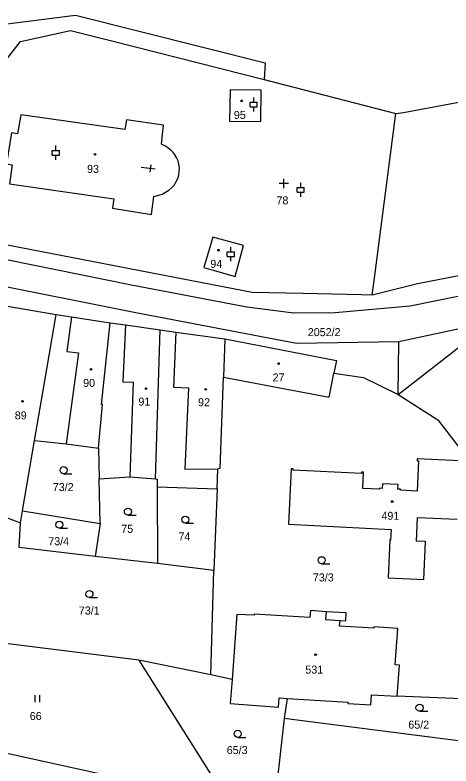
# Model space of a CAD drawing. Extents: x -794765 to -785424, y -1118958 to -1108731.
# Drawn here: x -788096.4 to -788003.9, y -1116478.9 to -1116319.5 of the extents above; entities that cross this region are included whole.
import ezdxf

# ---------------------------------------------------------------- set-up
doc = ezdxf.new("R2010")
doc.units = 0
for name, color, linetype in [('Level 66', 7, 'Continuous'), ('Level 75', 7, 'Continuous'), ('Level 76', 7, 'Continuous'), ('Level 77', 7, 'Continuous'), ('Level 79', 7, 'Continuous')]:
    doc.layers.add(name, color=color, linetype=linetype)

msp = doc.modelspace()

# ---------------------------------------------------------------- linework, layer by layer
at = {"layer": 'Level 66'}
for p, q in [((-788045.73, -1116337.98), (-788045.73, -1116336.98)), ((-788046.48, -1116337.98), (-788044.98, -1116337.98)), ((-788046.48, -1116338.98), (-788046.48, -1116337.98)), ((-788046.48, -1116338.98), (-788044.98, -1116338.98)), ((-788045.73, -1116339.98), (-788045.73, -1116338.98)), ((-788044.98, -1116338.98), (-788044.98, -1116337.98)), ((-788087.74, -1116348.2), (-788087.74, -1116347.2)), ((-788088.49, -1116348.2), (-788086.99, -1116348.2)), ((-788088.49, -1116349.2), (-788088.49, -1116348.2)), ((-788086.99, -1116349.2), (-788086.99, -1116348.2)), ((-788088.49, -1116349.2), (-788086.99, -1116349.2)), ((-788087.74, -1116350.2), (-788087.74, -1116349.2)), ((-788039.34, -1116356.24), (-788039.34, -1116354.24)), ((-788035.76, -1116356.07), (-788035.76, -1116355.07)), ((-788038.34, -1116355.24), (-788040.34, -1116355.24)), ((-788036.51, -1116356.07), (-788035.01, -1116356.07)), ((-788036.51, -1116357.07), (-788036.51, -1116356.07)), ((-788035.01, -1116357.07), (-788035.01, -1116356.07)), ((-788036.51, -1116357.07), (-788035.01, -1116357.07)), ((-788035.76, -1116358.07), (-788035.76, -1116357.07)), ((-788050.6, -1116369.73), (-788050.6, -1116368.73)), ((-788051.35, -1116369.73), (-788049.85, -1116369.73)), ((-788051.35, -1116370.73), (-788051.35, -1116369.73)), ((-788051.35, -1116370.73), (-788049.85, -1116370.73)), ((-788050.6, -1116371.73), (-788050.6, -1116370.73)), ((-788049.85, -1116370.73), (-788049.85, -1116369.73)), ((-788086.09, -1116416.86), (-788084.34, -1116416.86)), ((-788072.45, -1116425.66), (-788070.7, -1116425.66)), ((-788086.98, -1116428.43), (-788085.23, -1116428.43)), ((-788060.25, -1116427.37), (-788058.5, -1116427.37)), ((-788031.33, -1116435.97), (-788029.58, -1116435.97)), ((-788080.61, -1116443.16), (-788078.86, -1116443.16)), ((-788092.14, -1116465.35), (-788092.14, -1116463.85)), ((-788091.14, -1116465.35), (-788091.14, -1116463.85)), ((-788010.56, -1116467.28), (-788008.81, -1116467.28)), ((-788049.14, -1116472.83), (-788047.39, -1116472.83))]:
    msp.add_line(p, q, dxfattribs=at)
for centre in [(-788086.09, -1116416.11), (-788072.45, -1116424.91), (-788060.25, -1116426.62), (-788086.98, -1116427.68), (-788031.33, -1116435.22), (-788080.61, -1116442.41), (-788010.56, -1116466.53), (-788049.14, -1116472.08)]:
    msp.add_circle(centre, 0.75, dxfattribs=at)
at = {"layer": 'Level 75'}
for p, q in [((-788043.51, -1116333.19), (-788015.56, -1116340.35)), ((-788066.61, -1116417.95), (-788065.62, -1116386.32)), ((-788015.12, -1116400.05), (-787998.34, -1116386.95)), ((-788051.87, -1116388.25), (-788052.17, -1116396.35)), ((-788015.12, -1116400.05), (-788014.95, -1116388.89)), ((-788094.82, -1116424.73), (-788092.26, -1116409.81)), ((-788078.71, -1116411.45), (-788078.56, -1116417.96)), ((-788078.34, -1116427.43), (-788078.56, -1116417.96)), ((-788066.2, -1116419.66), (-788053.5, -1116420.08)), ((-788066.2, -1116419.66), (-788066.14, -1116435.91)), ((-788053.5, -1116420.08), (-788054.21, -1116437.38)), ((-788103.93, -1116424.04), (-788095.26, -1116427.29)), ((-788095.26, -1116427.29), (-788094.82, -1116424.73)), ((-788094.82, -1116424.73), (-788078.34, -1116427.43)), ((-788078.34, -1116427.43), (-788079.41, -1116434.45)), ((-788066.14, -1116435.91), (-788079.41, -1116434.45)), ((-788054.21, -1116437.38), (-788066.14, -1116435.91)), ((-788054.85, -1116459.59), (-788054.21, -1116437.38)), ((-788070.15, -1116456.47), (-788108.88, -1116451.59)), ((-788054.85, -1116459.59), (-788070.15, -1116456.47)), ((-788050.33, -1116460.52), (-788054.85, -1116459.59)), ((-788038.67, -1116464.56), (-788039.3, -1116468.86)), ((-788039.3, -1116468.86), (-788041.37, -1116487.28)), ((-787990.75, -1116475.07), (-788039.3, -1116468.86))]:
    msp.add_line(p, q, dxfattribs=at)
for points in [[(-788110.98, -1116320.69), (-788100.4, -1116321.61), (-788083.57, -1116319.47), (-788043.34, -1116329.62), (-788043.51, -1116333.19)], [(-788104.08, -1116336.38), (-788095.27, -1116325.08), (-788084.6, -1116322.77), (-788075.84, -1116324.92), (-788043.51, -1116333.19)], [(-788044.2, -1116342.07), (-788044.15, -1116335.4), (-788050.76, -1116335.38), (-788050.87, -1116342.02), (-788044.2, -1116342.07)], [(-788015.56, -1116340.35), (-788013.98, -1116340.14), (-787987.86, -1116335.25)], [(-788104.08, -1116336.38), (-788108.05, -1116361.45), (-788105.63, -1116365.59), (-788103.61, -1116367.18), (-788046.1, -1116378.3), (-788038.81, -1116378.46), (-788035.35, -1116378.54), (-788022.85, -1116378.83), (-788020.59, -1116378.86)], [(-788065.34, -1116346.88), (-788064.86, -1116342.89), (-788072.76, -1116341.74), (-788073.06, -1116343.77), (-788095.19, -1116340.68), (-788095.84, -1116344.71), (-788097.16, -1116344.45), (-788098.21, -1116351.08), (-788097, -1116351.26), (-788097.58, -1116355.3), (-788075.44, -1116358.49), (-788075.73, -1116360.48), (-788067.47, -1116361.8), (-788066.97, -1116357.98)], [(-788020.59, -1116378.86), (-788020.25, -1116376.38), (-788015.56, -1116340.35)], [(-788066.97, -1116357.98), (-788066.16, -1116357.82), (-788065.37, -1116357.56), (-788065.18, -1116357.48), (-788064.44, -1116357.1), (-788063.75, -1116356.64), (-788063.13, -1116356.1), (-788062.57, -1116355.49), (-788062.18, -1116354.84), (-788061.87, -1116354.15), (-788061.66, -1116353.43), (-788061.54, -1116352.68), (-788061.52, -1116351.92), (-788061.61, -1116351.17), (-788061.79, -1116350.43), (-788062.14, -1116349.71), (-788062.57, -1116349.03), (-788062.78, -1116348.76), (-788063.33, -1116348.17), (-788063.94, -1116347.66), (-788064.62, -1116347.23), (-788065.34, -1116346.88)], [(-788279.68, -1116369.68), (-788255.51, -1116372.91), (-788222.27, -1116376.2), (-788184.96, -1116374.64), (-788169.09, -1116371.97), (-788125.59, -1116364.93), (-788118.03, -1116366.65), (-788103.88, -1116370.26), (-788071.66, -1116376.73), (-788047.19, -1116381.42), (-788037.25, -1116382.67), (-788028.44, -1116382.62), (-788012.56, -1116381.23), (-787982.57, -1116375.12), (-787957.81, -1116369.21), (-787938.9, -1116364.93), (-787918.57, -1116359.78), (-787902.51, -1116353.37)], [(-787873.99, -1116354.2), (-787897.15, -1116362.5), (-787902.61, -1116363.72), (-787928.65, -1116369.79), (-787960.17, -1116377.12), (-788014.95, -1116388.89)], [(-788054.45, -1116366.61), (-788056.36, -1116373.05), (-788049.67, -1116374.99), (-788047.89, -1116368.42), (-788054.45, -1116366.61)], [(-788020.59, -1116378.86), (-788011.01, -1116376.49), (-787983.27, -1116371.1)], [(-788014.95, -1116388.89), (-788036.64, -1116389.18), (-788070.79, -1116382.68), (-788103.44, -1116376.2), (-788117.24, -1116374.47), (-788120.83, -1116373.97), (-788135.12, -1116373.51), (-788155.68, -1116377.39), (-788186.34, -1116383.39), (-788190.87, -1116384.17), (-788201.33, -1116384.26), (-788234.5, -1116382.6)], [(-788103.27, -1116378.99), (-788098.18, -1116380.06), (-788098.42, -1116381.18), (-788087.66, -1116383.04)], [(-788092.26, -1116409.81), (-788090.51, -1116399.62), (-788087.66, -1116383.04)], [(-788087.66, -1116383.04), (-788084.4, -1116383.53), (-788076.2, -1116384.79)], [(-788078.71, -1116411.45), (-788077.83, -1116402.16), (-788078.08, -1116402.14), (-788076.2, -1116384.79)], [(-788076.2, -1116384.79), (-788072.94, -1116385.26), (-788065.62, -1116386.32)], [(-788065.62, -1116386.32), (-788062.27, -1116386.79), (-788051.87, -1116388.25)], [(-788051.87, -1116388.25), (-788028.19, -1116392.84), (-788028.72, -1116395.5)], [(-788053.5, -1116420.08), (-788053.33, -1116415.81), (-788052.88, -1116415.7), (-788052.17, -1116396.35)], [(-788052.17, -1116396.35), (-788029.75, -1116400.64), (-788028.72, -1116395.5)], [(-788028.72, -1116395.5), (-788022.48, -1116396.45), (-788015.12, -1116400.05)], [(-788015.12, -1116400.05), (-788006.65, -1116405.45), (-788000.06, -1116414.07), (-787995.42, -1116423.48), (-787992.45, -1116431.22), (-787989.3, -1116443.49), (-787985.23, -1116460.93), (-787984.99, -1116467.12)], [(-788092.26, -1116409.81), (-788085.52, -1116410.53), (-788078.71, -1116411.45)], [(-788002.01, -1116414.1), (-788011.05, -1116413.71), (-788011.07, -1116414.13), (-788010.78, -1116414.14), (-788011.08, -1116420.54), (-788014.63, -1116420.36), (-788014.62, -1116420.15), (-788015.15, -1116420.13), (-788015.1, -1116419.15), (-788018.43, -1116418.99), (-788018.48, -1116419.97), (-788019.03, -1116419.93), (-788019.03, -1116420.16), (-788022.58, -1116419.99), (-788022.42, -1116416.53), (-788022.85, -1116416.5), (-788022.87, -1116416.81), (-788037.36, -1116416.12), (-788037.35, -1116415.82)], [(-788037.35, -1116415.82), (-788037.79, -1116415.8), (-788038.33, -1116427.56), (-788016.58, -1116428.67), (-788016.7, -1116430.94), (-788016.86, -1116430.93), (-788017.2, -1116438.95), (-788009.63, -1116439.33), (-788009.29, -1116431.24), (-788011.21, -1116431.17), (-788010.98, -1116426.15), (-788002.56, -1116426.54)], [(-788078.56, -1116417.96), (-788072.05, -1116417.55), (-788066.61, -1116417.95)], [(-788066.61, -1116417.95), (-788066.21, -1116417.98), (-788066.2, -1116419.66)], [(-788079.41, -1116434.45), (-788095.52, -1116432.53), (-788095.26, -1116427.29)], [(-788015.27, -1116464.09), (-788014.84, -1116457.51), (-788015.74, -1116457.45), (-788015.19, -1116449.72), (-788020.27, -1116449.35), (-788020.29, -1116449.67), (-788027.56, -1116449.2), (-788027.43, -1116448.01), (-788026.2, -1116448.09), (-788026.1, -1116446.42), (-788030.4, -1116446.2), (-788033.68, -1116445.88), (-788033.83, -1116447.38), (-788045.64, -1116446.66), (-788045.66, -1116446.92), (-788049.32, -1116446.74), (-788050.33, -1116460.52)], [(-788070.15, -1116456.47), (-788052.14, -1116485), (-788052.25, -1116486.37)], [(-788050.33, -1116460.52), (-788050.71, -1116465.66), (-788040.5, -1116466.4), (-788040.37, -1116464.45), (-788038.67, -1116464.56)], [(-788038.67, -1116464.56), (-788025.73, -1116465.39), (-788025.75, -1116465.64), (-788020.88, -1116465.96), (-788020.73, -1116463.77), (-788015.27, -1116464.09)], [(-787990.75, -1116475.07), (-787991.37, -1116465.05), (-788015.27, -1116464.09)], [(-788052.25, -1116486.37), (-788061.11, -1116484.42), (-788104.94, -1116474.74)]]:
    msp.add_lwpolyline(points, dxfattribs=at)
at = {"layer": 'Level 77'}
for p, q in [((-788084.4, -1116383.53), (-788085.38, -1116390.88)), ((-788072.94, -1116385.26), (-788073.55, -1116397.34)), ((-788062.27, -1116386.79), (-788062.77, -1116398.45)), ((-788082.93, -1116391.21), (-788085.52, -1116410.53)), ((-788085.38, -1116390.88), (-788082.93, -1116391.21)), ((-788073.55, -1116397.34), (-788071.3, -1116397.43)), ((-788071.3, -1116397.43), (-788072.05, -1116417.55)), ((-788062.77, -1116398.45), (-788059.56, -1116398.6)), ((-788059.56, -1116398.6), (-788060.33, -1116415.86)), ((-788060.33, -1116415.86), (-788053.33, -1116415.81)), ((-788030.4, -1116446.2), (-788030.5, -1116447.83)), ((-788030.5, -1116447.83), (-788027.43, -1116448.01))]:
    msp.add_line(p, q, dxfattribs=at)
at = {"layer": 'Level 79'}
for p, q in [((-788066.67, -1116352.18), (-788069.65, -1116351.81)), ((-788067.58, -1116351.31), (-788067.76, -1116352.8))]:
    msp.add_line(p, q, dxfattribs=at)
for centre in [(-788048.3, -1116337.7), (-788079.44, -1116349.05), (-788053.21, -1116369.41), (-788040.44, -1116393.46), (-788080.29, -1116394.68), (-788068.61, -1116398.79), (-788055.93, -1116398.95), (-788094.81, -1116401.48), (-788016.36, -1116422.77), (-788032.62, -1116455.29)]:
    msp.add_circle(centre, 0.175, dxfattribs=at)

# ---------------------------------------------------------------- texts
at = {"layer": 'Level 76'}
for s, p in [('95', (-788049.96, -1116341.53)), ('93', (-788081.11, -1116352.99)), ('78', (-788040.92, -1116359.68)), ('94', (-788054.95, -1116373.16)), ('2052/2', (-788034.27, -1116387.65)), ('27', (-788041.74, -1116397.27)), ('90', (-788081.94, -1116398.43)), ('91', (-788070.21, -1116402.39)), ('92', (-788057.56, -1116402.53)), ('89', (-788096.45, -1116405.32)), ('73/2', (-788088.39, -1116420.55)), ('491', (-788018.64, -1116426.64)), ('75', (-788073.86, -1116429.41)), ('74', (-788061.72, -1116431.03)), ('73/4', (-788089.34, -1116432.04)), ('73/3', (-788033.19, -1116439.73)), ('73/1', (-788082.86, -1116446.75)), ('531', (-788034.79, -1116459.3)), ('66', (-788093.27, -1116469.15)), ('65/2', (-788012.94, -1116470.98)), ('65/3', (-788051.47, -1116476.38))]:
    msp.add_text(s, height=1.7, dxfattribs=at).set_placement(p)

doc.saveas('drawing.dxf')
